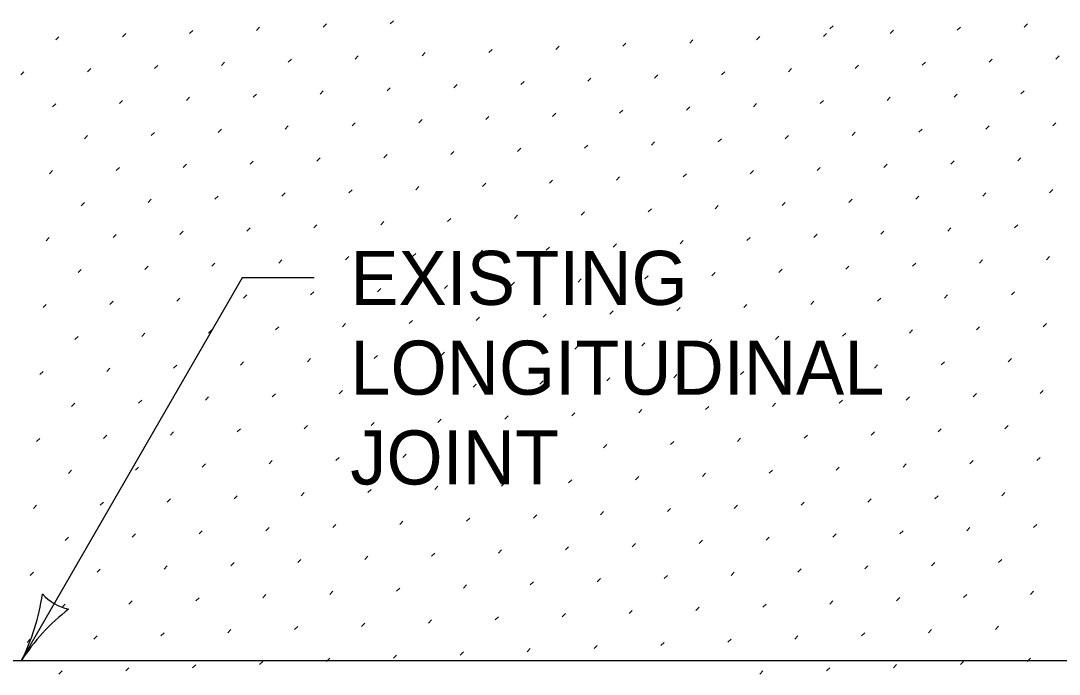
# Model space of a CAD drawing. Extents: x 49991.4 to 50021, y 49987.6 to 50011.4.
# Drawn here: x 50012.199 to 50013.352, y 49996.277 to 49997.002 of the extents above; entities that cross this region are included whole.
import ezdxf

# ---------------------------------------------------------------- set-up
doc = ezdxf.new("R2010")
doc.units = 0
for name, color, linetype in [('Level 1', 7, 'Continuous'), ('Level 10', 7, 'Continuous'), ('Level 2', 7, 'Continuous'), ('Level 3', 7, 'Continuous')]:
    doc.layers.add(name, color=color, linetype=linetype)

msp = doc.modelspace()

# ---------------------------------------------------------------- linework, layer by layer
at = {"layer": 'Level 1'}
msp.add_line((50013.9348, 49996.2915), (50011.6848, 49996.2915), dxfattribs=at)
at = {"layer": 'Level 10'}
for p, q in [((50012.5349, 49996.9946), (50012.5385, 49996.9982)), ((50012.6092, 49996.9982), (50012.6127, 49997.0017)), ((50013.0972, 49996.9926), (50013.1007, 49996.9961)), ((50013.3128, 49996.9947), (50013.3164, 49996.9982)), ((50012.3122, 49996.984), (50012.3157, 49996.9875)), ((50012.3864, 49996.9875), (50012.39, 49996.9911)), ((50012.4607, 49996.9911), (50012.4642, 49996.9946)), ((50013.0901, 49996.9841), (50013.0936, 49996.9876)), ((50013.1643, 49996.9876), (50013.1679, 49996.9912)), ((50013.2386, 49996.9912), (50013.2421, 49996.9947)), ((50012.2379, 49996.9805), (50012.2415, 49996.984)), ((50012.7931, 49996.9699), (50012.7966, 49996.9734)), ((50012.8673, 49996.9734), (50012.8709, 49996.977)), ((50012.9416, 49996.977), (50012.9451, 49996.9805)), ((50013.0158, 49996.9805), (50013.0194, 49996.9841)), ((50012.5703, 49996.9593), (50012.5738, 49996.9628)), ((50012.6446, 49996.9628), (50012.6481, 49996.9664)), ((50012.7188, 49996.9664), (50012.7223, 49996.9699)), ((50013.3482, 49996.9593), (50013.3517, 49996.9629)), ((50012.3475, 49996.9487), (50012.3511, 49996.9522)), ((50012.4218, 49996.9522), (50012.4253, 49996.9557)), ((50012.4961, 49996.9557), (50012.4996, 49996.9593)), ((50013.1254, 49996.9487), (50013.129, 49996.9523)), ((50013.1997, 49996.9523), (50013.2032, 49996.9558)), ((50013.2739, 49996.9558), (50013.2775, 49996.9593)), ((50012.199, 49996.9416), (50012.2026, 49996.9451)), ((50012.2733, 49996.9451), (50012.2768, 49996.9486)), ((50012.8284, 49996.9346), (50012.832, 49996.9381)), ((50012.9027, 49996.9381), (50012.9062, 49996.9416)), ((50012.9769, 49996.9416), (50012.9805, 49996.9452)), ((50013.0512, 49996.9452), (50013.0547, 49996.9487)), ((50012.6057, 49996.9239), (50012.6092, 49996.9275)), ((50012.6799, 49996.9275), (50012.6834, 49996.931)), ((50012.7542, 49996.931), (50012.7577, 49996.9345)), ((50012.3829, 49996.9133), (50012.3864, 49996.9168)), ((50012.4572, 49996.9168), (50012.4607, 49996.9204)), ((50012.5314, 49996.9204), (50012.5349, 49996.9239)), ((50013.1608, 49996.9134), (50013.1643, 49996.9169)), ((50013.235, 49996.9169), (50013.2386, 49996.9204)), ((50013.3093, 49996.9205), (50013.3128, 49996.924)), ((50012.2344, 49996.9062), (50012.2379, 49996.9097)), ((50012.3086, 49996.9098), (50012.3122, 49996.9133)), ((50012.938, 49996.9027), (50012.9416, 49996.9063)), ((50013.0123, 49996.9063), (50013.0158, 49996.9098)), ((50013.0865, 49996.9098), (50013.0901, 49996.9134)), ((50012.641, 49996.8886), (50012.6446, 49996.8921)), ((50012.7153, 49996.8921), (50012.7188, 49996.8956)), ((50012.7895, 49996.8957), (50012.7931, 49996.8992)), ((50012.8638, 49996.8992), (50012.8673, 49996.9027)), ((50012.4183, 49996.8779), (50012.4218, 49996.8815)), ((50012.4925, 49996.8815), (50012.496, 49996.885)), ((50012.5668, 49996.885), (50012.5703, 49996.8886)), ((50013.1961, 49996.878), (50013.1997, 49996.8815)), ((50013.2704, 49996.8816), (50013.2739, 49996.8851)), ((50013.3446, 49996.8851), (50013.3482, 49996.8886)), ((50012.2697, 49996.8709), (50012.2733, 49996.8744)), ((50012.344, 49996.8744), (50012.3475, 49996.8779)), ((50012.9734, 49996.8674), (50012.9769, 49996.8709)), ((50013.0476, 49996.8709), (50013.0512, 49996.8745)), ((50013.1219, 49996.8745), (50013.1254, 49996.878)), ((50012.7506, 49996.8568), (50012.7542, 49996.8603)), ((50012.8249, 49996.8603), (50012.8284, 49996.8638)), ((50012.8991, 49996.8638), (50012.9027, 49996.8674)), ((50012.4536, 49996.8426), (50012.4571, 49996.8461)), ((50012.5279, 49996.8461), (50012.5314, 49996.8497)), ((50012.6021, 49996.8497), (50012.6057, 49996.8532)), ((50012.6764, 49996.8532), (50012.6799, 49996.8567)), ((50013.2315, 49996.8427), (50013.235, 49996.8462)), ((50013.3058, 49996.8462), (50013.3093, 49996.8497)), ((50012.2309, 49996.832), (50012.2344, 49996.8355)), ((50012.3051, 49996.8355), (50012.3086, 49996.839)), ((50012.3794, 49996.839), (50012.3829, 49996.8426)), ((50013.0087, 49996.832), (50013.0123, 49996.8356)), ((50013.083, 49996.8356), (50013.0865, 49996.8391)), ((50013.1572, 49996.8391), (50013.1608, 49996.8426)), ((50012.786, 49996.8214), (50012.7895, 49996.8249)), ((50012.8602, 49996.8249), (50012.8638, 49996.8285)), ((50012.9345, 49996.8285), (50012.938, 49996.832)), ((50012.5632, 49996.8108), (50012.5668, 49996.8143)), ((50012.6375, 49996.8143), (50012.641, 49996.8179)), ((50012.7117, 49996.8179), (50012.7153, 49996.8214)), ((50013.3411, 49996.8108), (50013.3446, 49996.8144)), ((50012.2662, 49996.7966), (50012.2697, 49996.8001)), ((50012.3405, 49996.8001), (50012.344, 49996.8037)), ((50012.4147, 49996.8037), (50012.4182, 49996.8072)), ((50012.489, 49996.8072), (50012.4925, 49996.8108)), ((50013.0441, 49996.7967), (50013.0476, 49996.8002)), ((50013.1183, 49996.8002), (50013.1219, 49996.8038)), ((50013.1926, 49996.8038), (50013.1961, 49996.8073)), ((50013.2669, 49996.8073), (50013.2704, 49996.8108)), ((50012.8213, 49996.786), (50012.8249, 49996.7896)), ((50012.8956, 49996.7896), (50012.8991, 49996.7931)), ((50012.9698, 49996.7931), (50012.9734, 49996.7967)), ((50012.5986, 49996.7754), (50012.6021, 49996.779)), ((50012.6728, 49996.779), (50012.6764, 49996.7825)), ((50012.7471, 49996.7825), (50012.7506, 49996.786)), ((50012.3758, 49996.7648), (50012.3793, 49996.7683)), ((50012.4501, 49996.7683), (50012.4536, 49996.7719)), ((50012.5243, 49996.7719), (50012.5279, 49996.7754)), ((50013.1537, 49996.7649), (50013.1572, 49996.7684)), ((50013.228, 49996.7684), (50013.2315, 49996.7719)), ((50013.3022, 49996.7719), (50013.3057, 49996.7755)), ((50012.2273, 49996.7577), (50012.2308, 49996.7612)), ((50012.3016, 49996.7612), (50012.3051, 49996.7648)), ((50012.8567, 49996.7507), (50012.8602, 49996.7542)), ((50012.9309, 49996.7542), (50012.9345, 49996.7578)), ((50013.0052, 49996.7578), (50013.0087, 49996.7613)), ((50013.0794, 49996.7613), (50013.083, 49996.7649)), ((50012.6339, 49996.7401), (50012.6375, 49996.7436)), ((50012.7082, 49996.7436), (50012.7117, 49996.7471)), ((50012.7824, 49996.7471), (50012.786, 49996.7507)), ((50012.4112, 49996.7294), (50012.4147, 49996.733)), ((50012.4854, 49996.733), (50012.489, 49996.7365)), ((50012.5597, 49996.7365), (50012.5632, 49996.7401)), ((50013.1891, 49996.7295), (50013.1926, 49996.733)), ((50013.2633, 49996.733), (50013.2668, 49996.7366)), ((50013.3376, 49996.7366), (50013.3411, 49996.7401)), ((50012.2627, 49996.7223), (50012.2662, 49996.7259)), ((50012.3369, 49996.7259), (50012.3405, 49996.7294)), ((50012.9663, 49996.7189), (50012.9698, 49996.7224)), ((50013.0406, 49996.7224), (50013.0441, 49996.726)), ((50013.1148, 49996.726), (50013.1183, 49996.7295)), ((50012.6693, 49996.7047), (50012.6728, 49996.7082)), ((50012.7435, 49996.7082), (50012.7471, 49996.7118)), ((50012.8178, 49996.7118), (50012.8213, 49996.7153)), ((50012.892, 49996.7153), (50012.8956, 49996.7189)), ((50012.4465, 49996.6941), (50012.4501, 49996.6976)), ((50012.5208, 49996.6976), (50012.5243, 49996.7012)), ((50012.595, 49996.7012), (50012.5986, 49996.7047)), ((50013.2244, 49996.6941), (50013.2279, 49996.6977)), ((50013.2987, 49996.6977), (50013.3022, 49996.7012)), ((50012.2238, 49996.6835), (50012.2273, 49996.687)), ((50012.298, 49996.687), (50012.3016, 49996.6905)), ((50012.3723, 49996.6905), (50012.3758, 49996.6941)), ((50013.0017, 49996.6835), (50013.0052, 49996.6871)), ((50013.0759, 49996.6871), (50013.0794, 49996.6906)), ((50013.1502, 49996.6906), (50013.1537, 49996.6941)), ((50012.7789, 49996.6729), (50012.7824, 49996.6764)), ((50012.8531, 49996.6764), (50012.8567, 49996.68)), ((50012.9274, 49996.68), (50012.9309, 49996.6835)), ((50012.4819, 49996.6587), (50012.4854, 49996.6623)), ((50012.5561, 49996.6623), (50012.5597, 49996.6658)), ((50012.6304, 49996.6658), (50012.6339, 49996.6693)), ((50012.7046, 49996.6694), (50012.7082, 49996.6729)), ((50013.2598, 49996.6588), (50013.2633, 49996.6623)), ((50013.334, 49996.6623), (50013.3376, 49996.6659)), ((50012.2591, 49996.6481), (50012.2627, 49996.6516)), ((50012.3334, 49996.6516), (50012.3369, 49996.6552)), ((50012.4076, 49996.6552), (50012.4112, 49996.6587)), ((50013.037, 49996.6482), (50013.0405, 49996.6517)), ((50013.1113, 49996.6517), (50013.1148, 49996.6552)), ((50013.1855, 49996.6553), (50013.1891, 49996.6588)), ((50012.8142, 49996.6375), (50012.8178, 49996.6411)), ((50012.8885, 49996.6411), (50012.892, 49996.6446)), ((50012.9628, 49996.6446), (50012.9663, 49996.6482)), ((50012.5172, 49996.6234), (50012.5208, 49996.6269)), ((50012.5915, 49996.6269), (50012.595, 49996.6304)), ((50012.6657, 49996.6305), (50012.6693, 49996.634)), ((50012.74, 49996.634), (50012.7435, 49996.6375)), ((50013.2951, 49996.6234), (50013.2987, 49996.627)), ((50012.2945, 49996.6127), (50012.298, 49996.6163)), ((50012.3687, 49996.6163), (50012.3723, 49996.6198)), ((50012.443, 49996.6198), (50012.4465, 49996.6234)), ((50013.0724, 49996.6128), (50013.0759, 49996.6163)), ((50013.1466, 49996.6164), (50013.1502, 49996.6199)), ((50013.2209, 49996.6199), (50013.2244, 49996.6234)), ((50012.2202, 49996.6092), (50012.2238, 49996.6127)), ((50012.8496, 49996.6022), (50012.8531, 49996.6057)), ((50012.9239, 49996.6057), (50012.9274, 49996.6093)), ((50012.9981, 49996.6093), (50013.0016, 49996.6128)), ((50012.6268, 49996.5916), (50012.6304, 49996.5951)), ((50012.7011, 49996.5951), (50012.7046, 49996.5986)), ((50012.7754, 49996.5986), (50012.7789, 49996.6022)), ((50012.3298, 49996.5774), (50012.3334, 49996.5809)), ((50012.4041, 49996.5809), (50012.4076, 49996.5845)), ((50012.4783, 49996.5845), (50012.4819, 49996.588)), ((50012.5526, 49996.588), (50012.5561, 49996.5915)), ((50013.1077, 49996.5775), (50013.1113, 49996.581)), ((50013.182, 49996.581), (50013.1855, 49996.5845)), ((50013.2562, 49996.5845), (50013.2598, 49996.5881)), ((50013.3305, 49996.5881), (50013.334, 49996.5916)), ((50012.2556, 49996.5738), (50012.2591, 49996.5774)), ((50012.885, 49996.5668), (50012.8885, 49996.5704)), ((50012.9592, 49996.5704), (50012.9627, 49996.5739)), ((50013.0335, 49996.5739), (50013.037, 49996.5774)), ((50012.6622, 49996.5562), (50012.6657, 49996.5597)), ((50012.7365, 49996.5597), (50012.74, 49996.5633)), ((50012.8107, 49996.5633), (50012.8142, 49996.5668)), ((50012.4394, 49996.5456), (50012.443, 49996.5491)), ((50012.5137, 49996.5491), (50012.5172, 49996.5527)), ((50012.5879, 49996.5527), (50012.5915, 49996.5562)), ((50013.2173, 49996.5456), (50013.2209, 49996.5492)), ((50013.2916, 49996.5492), (50013.2951, 49996.5527)), ((50012.2167, 49996.5349), (50012.2202, 49996.5385)), ((50012.2909, 49996.5385), (50012.2945, 49996.542)), ((50012.3652, 49996.542), (50012.3687, 49996.5456)), ((50012.9203, 49996.5315), (50012.9239, 49996.535)), ((50012.9946, 49996.535), (50012.9981, 49996.5386)), ((50013.0688, 49996.5386), (50013.0724, 49996.5421)), ((50013.1431, 49996.5421), (50013.1466, 49996.5456)), ((50012.6976, 49996.5208), (50012.7011, 49996.5244)), ((50012.7718, 49996.5244), (50012.7753, 49996.5279)), ((50012.8461, 49996.5279), (50012.8496, 49996.5315)), ((50012.4748, 49996.5102), (50012.4783, 49996.5138)), ((50012.549, 49996.5138), (50012.5526, 49996.5173)), ((50012.6233, 49996.5173), (50012.6268, 49996.5208)), ((50013.2527, 49996.5103), (50013.2562, 49996.5138)), ((50013.3269, 49996.5138), (50013.3305, 49996.5174)), ((50012.252, 49996.4996), (50012.2556, 49996.5031)), ((50012.3263, 49996.5031), (50012.3298, 49996.5067)), ((50012.4005, 49996.5067), (50012.4041, 49996.5102)), ((50013.0299, 49996.4997), (50013.0335, 49996.5032)), ((50013.1042, 49996.5032), (50013.1077, 49996.5067)), ((50013.1784, 49996.5067), (50013.182, 49996.5103)), ((50012.7329, 49996.4855), (50012.7364, 49996.489)), ((50012.8072, 49996.489), (50012.8107, 49996.4926)), ((50012.8814, 49996.4926), (50012.885, 49996.4961)), ((50012.9557, 49996.4961), (50012.9592, 49996.4997)), ((50012.5102, 49996.4749), (50012.5137, 49996.4784)), ((50012.5844, 49996.4784), (50012.5879, 49996.4819)), ((50012.6587, 49996.4819), (50012.6622, 49996.4855)), ((50013.288, 49996.4749), (50013.2916, 49996.4785)), ((50012.2874, 49996.4642), (50012.2909, 49996.4678)), ((50012.3616, 49996.4678), (50012.3652, 49996.4713)), ((50012.4359, 49996.4713), (50012.4394, 49996.4749)), ((50013.0653, 49996.4643), (50013.0688, 49996.4678)), ((50013.1395, 49996.4678), (50013.1431, 49996.4714)), ((50013.2138, 49996.4714), (50013.2173, 49996.4749)), ((50012.2131, 49996.4607), (50012.2167, 49996.4642)), ((50012.8425, 49996.4537), (50012.8461, 49996.4572)), ((50012.9168, 49996.4572), (50012.9203, 49996.4608)), ((50012.991, 49996.4608), (50012.9946, 49996.4643)), ((50012.5455, 49996.4395), (50012.549, 49996.443)), ((50012.6198, 49996.443), (50012.6233, 49996.4466)), ((50012.694, 49996.4466), (50012.6975, 49996.4501)), ((50012.7683, 49996.4501), (50012.7718, 49996.4537)), ((50013.3234, 49996.4396), (50013.3269, 49996.4431)), ((50012.3227, 49996.4289), (50012.3263, 49996.4324)), ((50012.397, 49996.4324), (50012.4005, 49996.436)), ((50012.4713, 49996.436), (50012.4748, 49996.4395)), ((50013.1006, 49996.4289), (50013.1042, 49996.4325)), ((50013.1749, 49996.4325), (50013.1784, 49996.436)), ((50013.2491, 49996.436), (50013.2527, 49996.4396)), ((50012.2485, 49996.4253), (50012.252, 49996.4289)), ((50012.8779, 49996.4183), (50012.8814, 49996.4219)), ((50012.9521, 49996.4219), (50012.9557, 49996.4254)), ((50013.0264, 49996.4254), (50013.0299, 49996.4289)), ((50012.6551, 49996.4077), (50012.6586, 49996.4112)), ((50012.7294, 49996.4112), (50012.7329, 49996.4148)), ((50012.8036, 49996.4148), (50012.8072, 49996.4183)), ((50012.3581, 49996.3935), (50012.3616, 49996.3971)), ((50012.4324, 49996.3971), (50012.4359, 49996.4006)), ((50012.5066, 49996.4006), (50012.5101, 49996.4041)), ((50012.5809, 49996.4042), (50012.5844, 49996.4077)), ((50013.136, 49996.3936), (50013.1395, 49996.3971)), ((50013.2102, 49996.3971), (50013.2138, 49996.4007)), ((50013.2845, 49996.4007), (50013.288, 49996.4042)), ((50012.2096, 49996.3864), (50012.2131, 49996.39)), ((50012.2838, 49996.39), (50012.2874, 49996.3935)), ((50012.9132, 49996.383), (50012.9168, 49996.3865)), ((50012.9875, 49996.3865), (50012.991, 49996.39)), ((50013.0617, 49996.3901), (50013.0653, 49996.3936)), ((50012.6905, 49996.3723), (50012.694, 49996.3759)), ((50012.7647, 49996.3759), (50012.7683, 49996.3794)), ((50012.839, 49996.3794), (50012.8425, 49996.383)), ((50012.4677, 49996.3617), (50012.4712, 49996.3652)), ((50012.542, 49996.3653), (50012.5455, 49996.3688)), ((50012.6162, 49996.3688), (50012.6198, 49996.3723)), ((50013.1713, 49996.3582), (50013.1749, 49996.3618)), ((50013.2456, 49996.3618), (50013.2491, 49996.3653)), ((50013.3199, 49996.3653), (50013.3234, 49996.3689)), ((50012.245, 49996.3511), (50012.2485, 49996.3546)), ((50012.3192, 49996.3546), (50012.3227, 49996.3582)), ((50012.3935, 49996.3582), (50012.397, 49996.3617)), ((50012.9486, 49996.3476), (50012.9521, 49996.3511)), ((50013.0228, 49996.3512), (50013.0264, 49996.3547)), ((50013.0971, 49996.3547), (50013.1006, 49996.3582)), ((50012.7258, 49996.337), (50012.7294, 49996.3405)), ((50012.8001, 49996.3405), (50012.8036, 49996.3441)), ((50012.8743, 49996.3441), (50012.8779, 49996.3476)), ((50012.5031, 49996.3264), (50012.5066, 49996.3299)), ((50012.5773, 49996.3299), (50012.5809, 49996.3334)), ((50012.6516, 49996.3334), (50012.6551, 49996.337)), ((50013.281, 49996.3264), (50013.2845, 49996.33)), ((50012.2061, 49996.3122), (50012.2096, 49996.3157)), ((50012.2803, 49996.3157), (50012.2838, 49996.3193)), ((50012.3546, 49996.3193), (50012.3581, 49996.3228)), ((50012.4288, 49996.3228), (50012.4323, 49996.3263)), ((50012.9839, 49996.3123), (50012.9875, 49996.3158)), ((50013.0582, 49996.3158), (50013.0617, 49996.3193)), ((50013.1324, 49996.3193), (50013.136, 49996.3229)), ((50013.2067, 49996.3229), (50013.2102, 49996.3264)), ((50012.7612, 49996.3016), (50012.7647, 49996.3052)), ((50012.8354, 49996.3052), (50012.839, 49996.3087)), ((50012.9097, 49996.3087), (50012.9132, 49996.3122)), ((50012.5384, 49996.291), (50012.542, 49996.2945)), ((50012.6127, 49996.2945), (50012.6162, 49996.2981)), ((50012.6869, 49996.2981), (50012.6905, 49996.3016)), ((50013.3163, 49996.2911), (50013.3198, 49996.2946)), ((50012.3157, 49996.2804), (50012.3192, 49996.2839)), ((50012.3899, 49996.2839), (50012.3934, 49996.2874)), ((50012.4642, 49996.2875), (50012.4677, 49996.291)), ((50013.0935, 49996.2804), (50013.0971, 49996.284)), ((50013.1678, 49996.284), (50013.1713, 49996.2875)), ((50013.2421, 49996.2875), (50013.2456, 49996.2911)), ((50012.2414, 49996.2768), (50012.2449, 49996.2804)), ((50013.0193, 49996.2769), (50013.0228, 49996.2804))]:
    msp.add_line(p, q, dxfattribs=at)
at = {"layer": 'Level 3'}
for p, q in [((50012.4449, 49996.7165), (50012.1996, 49996.2915)), ((50012.5249, 49996.7165), (50012.4449, 49996.7165))]:
    msp.add_line(p, q, dxfattribs=at)
for centre, radius, start, end in [((50011.9923, 49996.3979), 0.233, 332.8273, 352.0772), ((50012.2637, 49996.4026), 0.0548, 222.1388, 257.8612), ((50012.3874, 49996.1725), 0.2223, 127.456, 147.6395)]:
    msp.add_arc(centre, radius, start, end, dxfattribs=at)

# ---------------------------------------------------------------- texts
at = {"layer": 'Level 2'}
for s, p in [('EXISTING', (50012.5649, 49996.6865)), ('LONGITUDINAL', (50012.5649, 49996.5869)), ('JOINT', (50012.5649, 49996.4873))]:
    msp.add_text(s, height=0.06, dxfattribs=at).set_placement(p)

doc.saveas('drawing.dxf')
